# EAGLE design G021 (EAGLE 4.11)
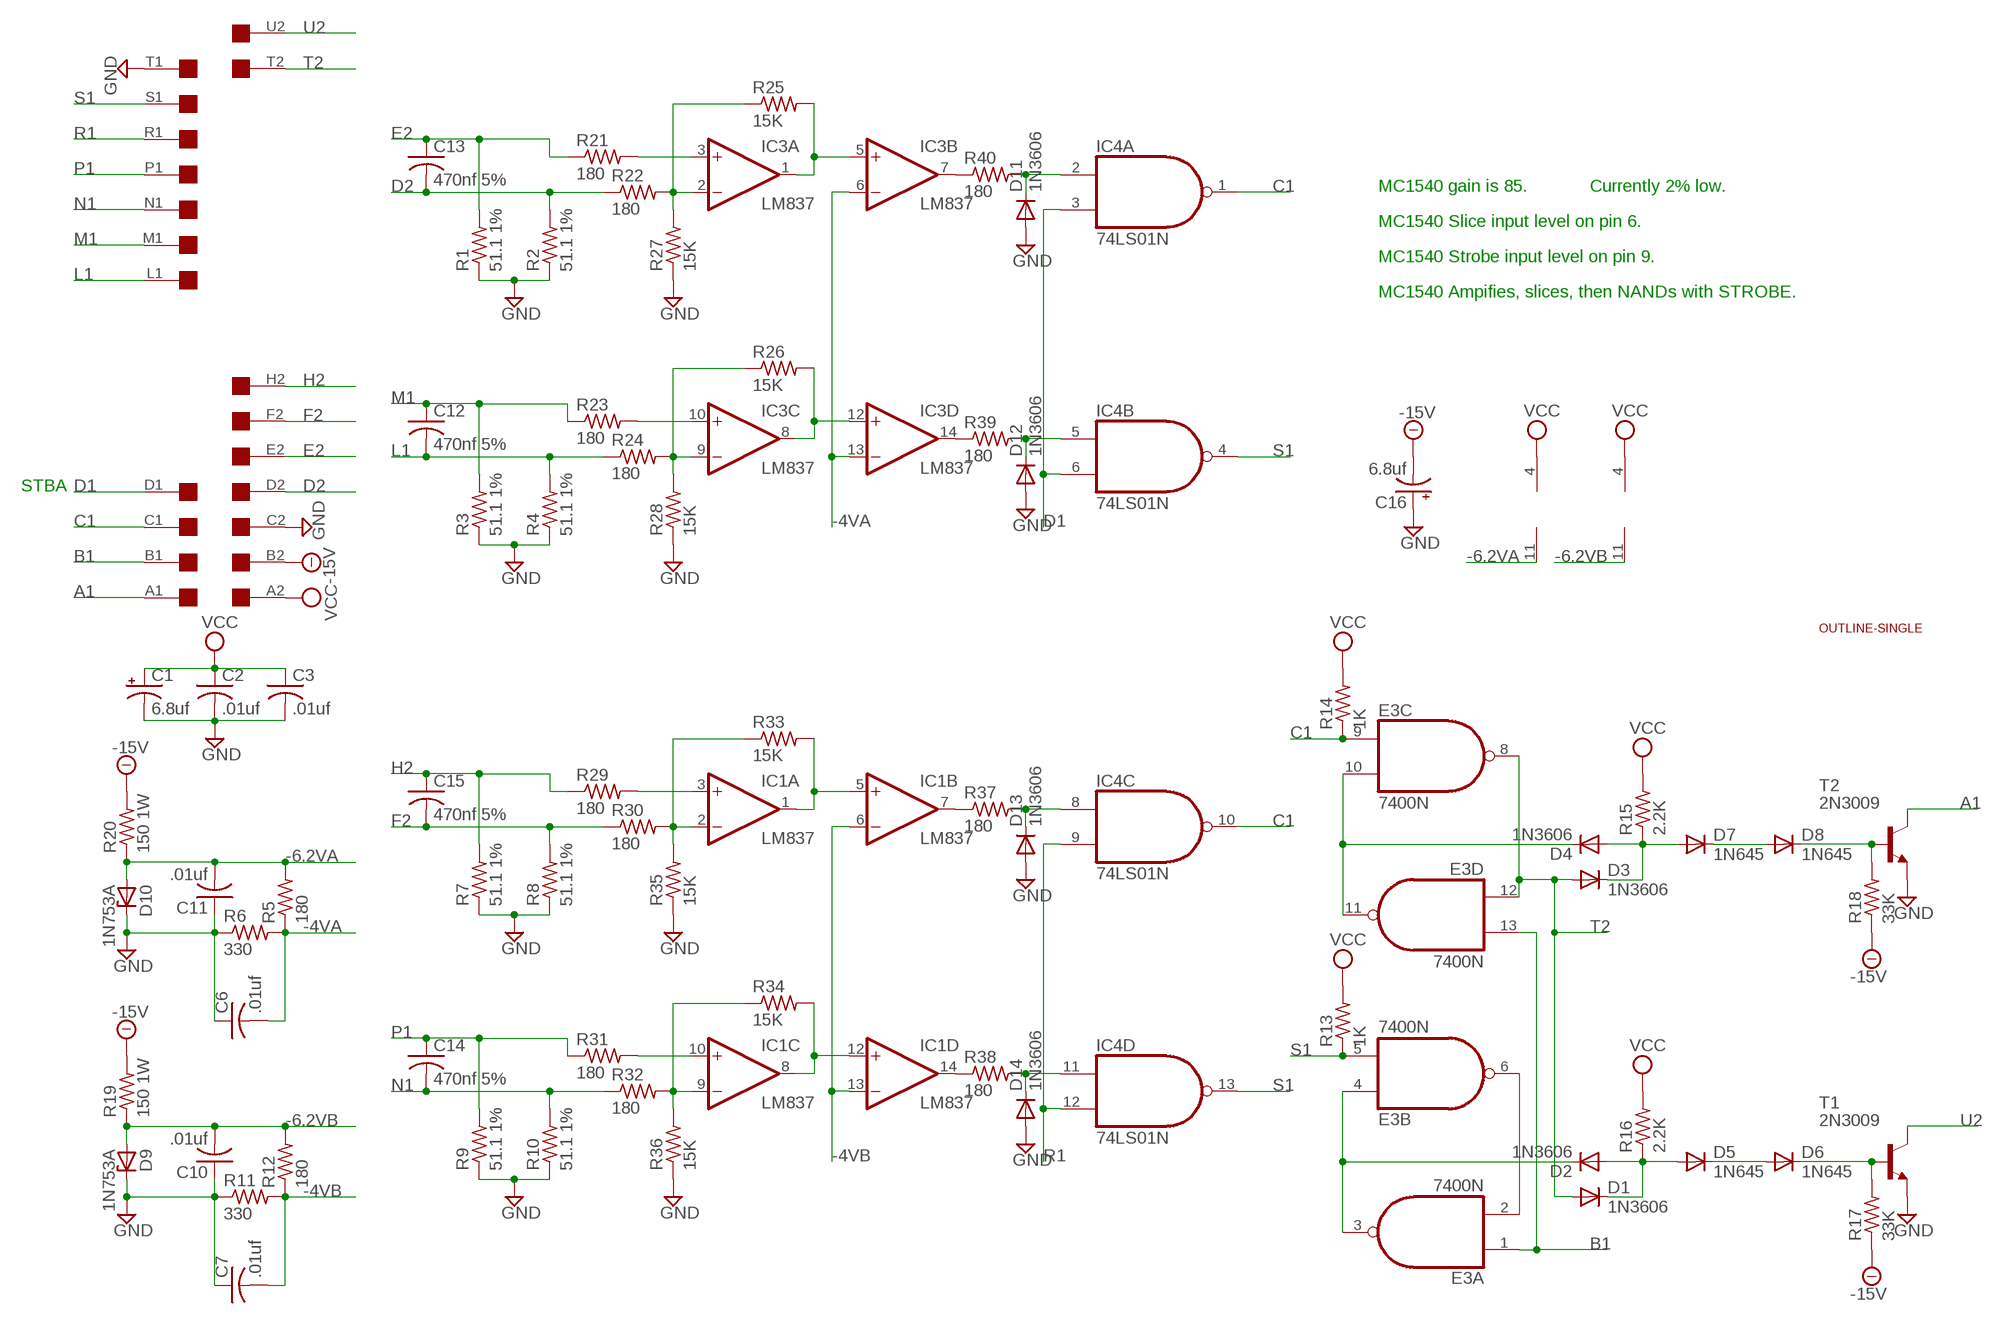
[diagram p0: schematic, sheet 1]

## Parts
C1  6.8uf  CPOL-USE15-5AXIAL  [E15-5]
C2  .01uf  C-US050-025X075  [C050-025X075]
C3  .01uf  C-US050-025X075  [C050-025X075]
C6  .01uf  C-US050-025X075  [C050-025X075]
C7  .01uf  C-US050-025X075  [C050-025X075]
C10  .01uf  C-US050-025X075  [C050-025X075]
C11  .01uf  C-US050-025X075  [C050-025X075]
C12  470nf 5%  C-US050-025X075  [C050-025X075]
C13  470nf 5%  C-US050-025X075  [C050-025X075]
C14  470nf 5%  C-US050-025X075  [C050-025X075]
C15  470nf 5%  C-US050-025X075  [C050-025X075]
C16  6.8uf  CPOL-USE15-5AXIAL  [E15-5]
D1  1N3606  1N4148  [DO35-10]
D2  1N3606  1N4148  [DO35-10]
D3  1N3606  1N4148  [DO35-10]
D4  1N3606  1N4148  [DO35-10]
D5  1N645  1N4148  [DO35-10]
D6  1N645  1N4148  [DO35-10]
D7  1N645  1N4148  [DO35-10]
D8  1N645  1N4148  [DO35-10]
D9  1N753A  ZENER-DIODEF126-10  [F126Z10]
D10  1N753A  ZENER-DIODEF126-10  [F126Z10]
D11  1N3606  1N4148  [DO35-10]
D12  1N3606  1N4148  [DO35-10]
D13  1N3606  1N4148  [DO35-10]
D14  1N3606  1N4148  [DO35-10]
E3  7400N  [DIL14]
IC1  LM837  OP11P  [DIL14]
IC3  LM837  OP11P  [DIL14]
IC4  74LS01N  [DIL14]
R1  51.1 1%  R-US_0207/10  [0207/10]
R2  51.1 1%  R-US_0207/10  [0207/10]
R3  51.1 1%  R-US_0207/10  [0207/10]
R4  51.1 1%  R-US_0207/10  [0207/10]
R5  180  R-US_0207/10  [0207/10]
R6  330  R-US_0207/10  [0207/10]
R7  51.1 1%  R-US_0207/10  [0207/10]
R8  51.1 1%  R-US_0207/10  [0207/10]
R9  51.1 1%  R-US_0207/10  [0207/10]
R10  51.1 1%  R-US_0207/10  [0207/10]
R11  330  R-US_0207/10  [0207/10]
R12  180  R-US_0207/10  [0207/10]
R13  1K  R-US_0207/10  [0207/10]
R14  1K  R-US_0207/10  [0207/10]
R15  2.2K  R-US_0207/10  [0207/10]
R16  2.2K  R-US_0207/10  [0207/10]
R17  33K  R-US_0207/10  [0207/10]
R18  33K  R-US_0207/10  [0207/10]
R19  150 1W  R-US_0414/15  [0414/15]
R20  150 1W  R-US_0414/15  [0414/15]
R21  180  R-US_0207/10  [0207/10]
R22  180  R-US_0207/10  [0207/10]
R23  180  R-US_0207/10  [0207/10]
R24  180  R-US_0207/10  [0207/10]
R25  15K  R-US_0207/10  [0207/10]
R26  15K  R-US_0207/10  [0207/10]
R27  15K  R-US_0207/10  [0207/10]
R28  15K  R-US_0207/10  [0207/10]
R29  180  R-US_0207/10  [0207/10]
R30  180  R-US_0207/10  [0207/10]
R31  180  R-US_0207/10  [0207/10]
R32  180  R-US_0207/10  [0207/10]
R33  15K  R-US_0207/10  [0207/10]
R34  15K  R-US_0207/10  [0207/10]
R35  15K  R-US_0207/10  [0207/10]
R36  15K  R-US_0207/10  [0207/10]
R37  180  R-US_0207/10  [0207/10]
R38  180  R-US_0207/10  [0207/10]
R39  180  R-US_0207/10  [0207/10]
R40  180  R-US_0207/10  [0207/10]
T1  2N3009  2N3565  [TO92]
T2  2N3009  2N3565  [TO92]
U$1  SINGLE  [EDGE-CON2]
U$2  OUTLINE-SINGLE  [SINGLE]

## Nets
-4VA: C6.2 IC3.6(B:-IN) IC3.13(D:-IN) R5.1 R6.2
-4VB: C7.2 IC1.6(B:-IN) IC1.13(D:-IN) R11.2 R12.1
-6.2VA: C11.2 D10.A IC3.11(P:V-) R5.2 R20.1
-6.2VB: C10.2 D9.A IC1.11(P:V-) R12.2 R19.1
-15V: C16.- R17.1 R18.1 R19.2 R20.2 U$1.B2
A1: T2.1(C) U$1.A1
B1: E3.1(A:I0) E3.13(D:I1) U$1.B1
C1: E3.9(C:I0) IC4.1(A:O) IC4.10(C:O) R14.1 U$1.C1
D1: IC4.3(A:I1) IC4.6(B:I1) U$1.D1
D2: C13.2 R2.2 R22.1 U$1.D2
E2: C13.1 R1.2 R21.1 U$1.E2
F2: C15.2 R8.2 R30.1 U$1.F2
GND: C1.- C2.2 C3.2 C6.1 C7.1 C10.1 C11.1 C16.+ D9.C D10.C D11.A D12.A D13.A D14.A R1.1 R2.1 R3.1 R4.1 R6.1 R7.1 R8.1 R9.1 R10.1 R11.1 R27.1 R28.1 R35.1 R36.1 T1.3(E) T2.3(E) U$1.C2 U$1.T1
H2: C15.1 R7.2 R29.1 U$1.H2
L1: C12.2 R4.2 R24.1 U$1.L1
M1: C12.1 R3.2 R23.1 U$1.M1
N1: C14.2 R10.2 R32.1 U$1.N1
N$1: IC3.7(B:OUT) R40.1
N$2: IC3.14(D:OUT) R39.1
N$3: IC1.7(B:OUT) R37.1
N$4: IC1.14(D:OUT) R38.1
N$5: IC3.8(C:OUT) IC3.12(D:+IN) R26.2
N$6: D1.C D2.A D5.A R16.1
N$7: D4.C E3.10(C:I1) E3.11(D:O)
N$8: D2.C E3.3(A:O) E3.4(B:I0)
N$9: E3.2(A:I1) E3.6(B:O)
N$10: D3.C D4.A D7.A R15.1
N$11: D7.C D8.A
N$12: D5.C D6.A
N$13: D8.C R18.2 T2.2(B)
N$14: D6.C R17.2 T1.2(B)
N$15: IC3.1(A:OUT) IC3.5(B:+IN) R25.2
N$20: IC3.9(C:-IN) R24.2 R26.1 R28.2
N$21: IC3.10(C:+IN) R23.2
N$22: IC3.2(A:-IN) R22.2 R25.1 R27.2
N$23: IC3.3(A:+IN) R21.2
N$24: IC1.8(C:OUT) IC1.12(D:+IN) R34.2
N$25: IC1.1(A:OUT) IC1.5(B:+IN) R33.2
N$30: IC1.9(C:-IN) R32.2 R34.1 R36.2
N$31: IC1.10(C:+IN) R31.2
N$32: IC1.2(A:-IN) R30.2 R33.1 R35.2
N$33: IC1.3(A:+IN) R29.2
N$34: D11.C IC4.2(A:I0) R40.2
N$35: D12.C IC4.5(B:I0) R39.2
N$36: D14.C IC4.11(D:I0) R38.2
N$37: D13.C IC4.8(C:I0) R37.2
P1: C14.1 R9.2 R31.1 U$1.P1
R1: IC4.9(C:I1) IC4.12(D:I1) U$1.R1
S1: E3.5(B:I1) IC4.4(B:O) IC4.13(D:O) R13.1 U$1.S1
T2: D1.A D3.A E3.8(C:O) E3.12(D:I0) U$1.T2
U2: T1.1(C) U$1.U2
VCC [supply]: C1.+ C2.1 C3.1 IC1.4(P:V+) IC3.4(P:V+) R13.2 R14.2 R15.2 R16.2 U$1.A2
Unconnected: U$1.E1 U$1.F1 U$1.H1 U$1.J1 U$1.J2 U$1.K1 U$1.K2 U$1.L2 U$1.M2 U$1.N2 U$1.P2 U$1.R2 U$1.S2 U$1.U1 U$1.V1 U$1.V2

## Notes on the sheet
- MC1540 gain is 85. | Currently 2% low.
- MC1540 Slice input level on pin 6.
- MC1540 Strobe input level on pin 9.
- MC1540 Ampifies, slices, then NANDs with STROBE.
- STBA

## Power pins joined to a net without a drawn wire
GND: E3.7(P:GND) IC4.7(P:GND)
VCC: E3.14(P:VCC) IC4.14(P:VCC)

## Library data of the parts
C1 C16 = rcl:CPOL-US: POLARIZED CAPACITOR, American symbol
C2 C3 C6 C7 C10-C15 = rcl:C-US: CAPACITOR, American symbol
D1-D8 D11-D14 = diode:1N4148: DIODE
D9 D10 = diode:ZENER-DIODE: Z-Diode
E3 = 74xx-us:74*00: Quad 2-input NAND gate
IC1 IC3 = linear:OP11: Quad Low-Offset Low-Power OP AMP The OP-11 is pin compatible with the OP-400 , LM148, HA4741, RM4156, and LT1014 operational amplifiers source http://products.analog.com/products/info.asp?product=OP400
IC4 = 74xx-us:74*01: Quad 2-input NAND gate, open collector
R1-R40 = rcl:R-US_: RESISTOR, American symbol
T1 T2 = transistor:2N3565: NPN TRANSISTOR
U$1 = dec-con:SINGLE: Double-Height DEC board
U$2 = dec-con:OUTLINE-*: Board outlines for DEC boards.

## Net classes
1 supply: width 0.762 mm, drill 0.508 mm

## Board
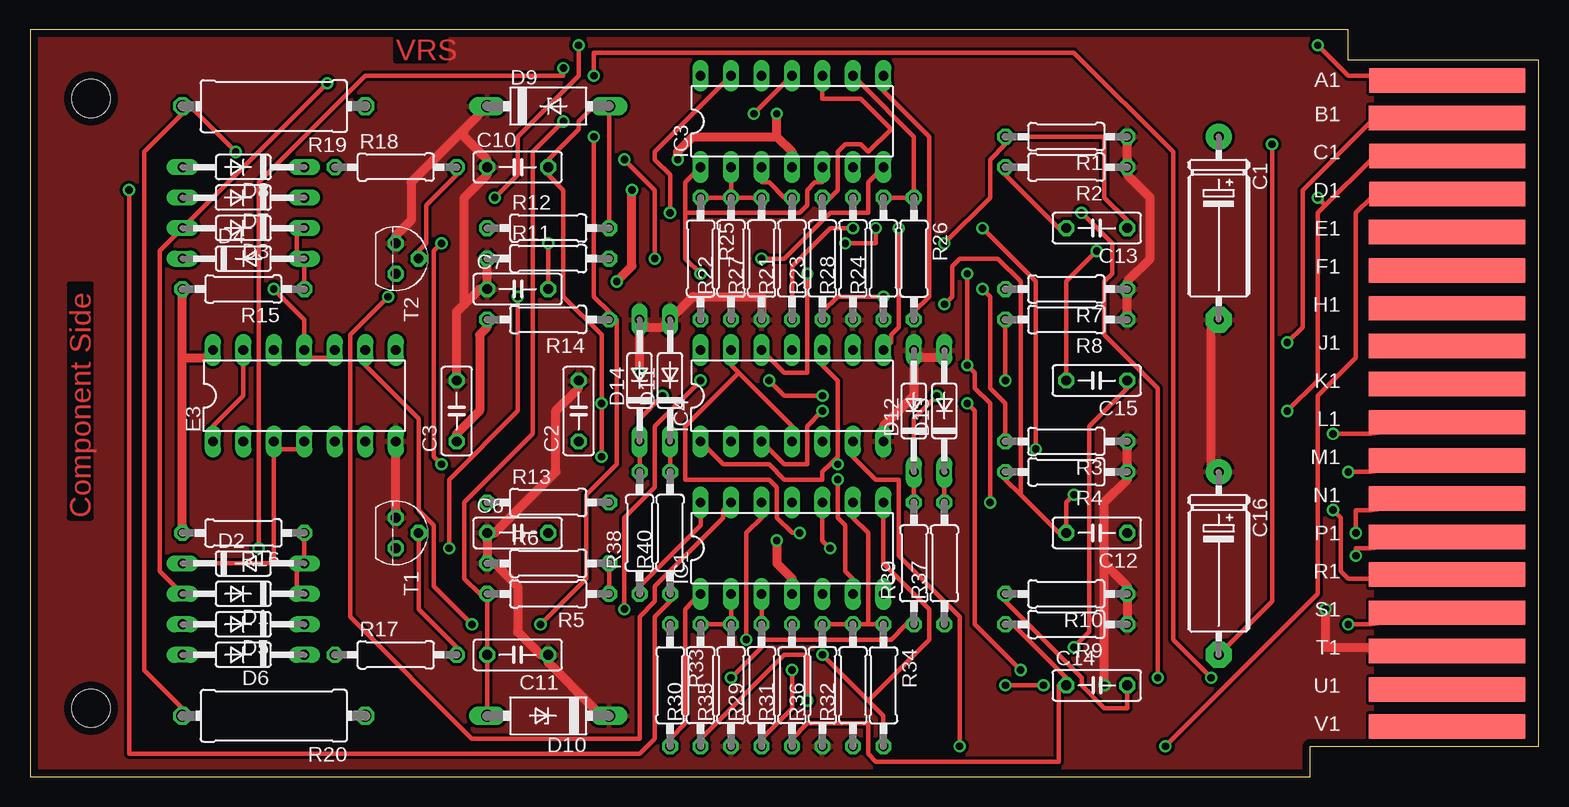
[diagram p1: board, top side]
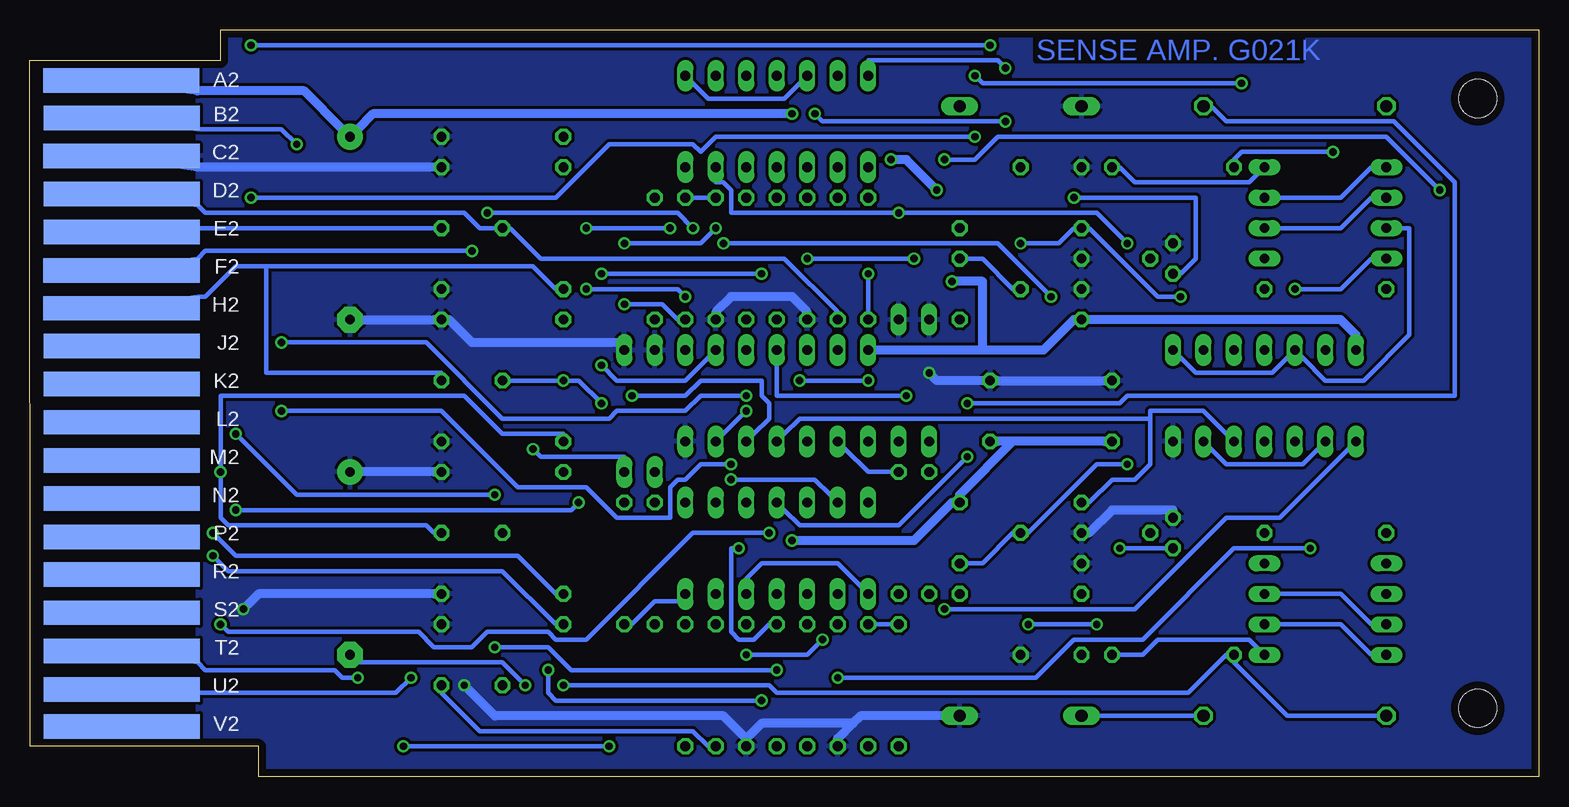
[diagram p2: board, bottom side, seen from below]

Size 125.73 x 62.23 mm. Coordinates in mm from the lower left corner, seen from the top.
Copper layers (1*16): Top 0.035mm / dielectric 1.5mm / Bottom 0.035mm
Design rules "10mils": minimum track width 10mil, minimum drill 24mil, track to track 10mil, track to pad 10mil, pad to pad 10mil, via to via 10mil, smd to smd 10mil, copper to edge 25mil, drill to drill 10mil, minimum pad ring 10mil, minimum via ring 8mil, stop-mask expansion 0mil, vias tented up to drill 0mil, thermal gap 10mil

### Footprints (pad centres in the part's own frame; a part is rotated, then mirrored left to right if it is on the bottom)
E15-5 = drill 0.813 pad 2.159 round: + -7.62,0 | drill 0.813 pad 2.159 octagon: - 7.62,0
C050-025X075 = drill 0.813 octagon: 1 -2.54,0; 2 2.54,0
DO35-10 = drill 0.813 long: A 5.08,0; C -5.08,0
F126Z10 = drill 1.016 long: A 5.08,0; C -5.08,0
DIL14 = drill 0.813 long: 1 -7.62,-3.81; 2 -5.08,-3.81; 3 -2.54,-3.81; 4 0,-3.81; 5 2.54,-3.81; 6 5.08,-3.81; 7 7.62,-3.81; 8 7.62,3.81; 9 5.08,3.81; 10 2.54,3.81; 11 0,3.81; 12 -2.54,3.81; 13 -5.08,3.81; 14 -7.62,3.81
0207/10 = drill 0.813 octagon: 1 -5.08,0; 2 5.08,0
0414/15 = drill 1.016 octagon: 1 -7.62,0; 2 7.62,0
TO92 = drill 0.813 octagon: 1 1.27,0; 2 0,1.905; 3 -1.27,0
EDGE-CON2 = smd 13.017 x 2.032: A1 7.633,4.207; B1 7.639,7.327; C1 7.636,10.489; D1 7.633,13.665; E1 7.642,16.84; F1 7.642,20.041; H1 7.642,23.19; J1 7.642,26.34; K1 7.642,29.515; L1 7.642,32.69; M1 7.642,35.89; N1 7.642,39.04; P1 7.642,42.24; R1 7.642,45.39; S1 7.642,48.565; T1 7.642,51.74; U1 7.642,54.966; V1 7.642,58.026 | smd 13.017 x 2.032 bottom: A2 7.614,4.207; B2 7.642,7.328; C2 7.617,10.49; D2 7.642,13.665; E2 7.642,16.84; F2 7.617,20.041; H2 7.617,23.19; J2 7.642,26.34; K2 7.642,29.515; L2 7.642,32.69; M2 7.642,35.89; N2 7.642,39.04; P2 7.642,42.24; R2 7.642,45.39; S2 7.642,48.565; T2 7.642,51.74; U2 7.642,54.966; V2 7.642,58.026
SINGLE = hole 3.175: 120.65,56.515; 120.65,5.715

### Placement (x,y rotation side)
C1  99.06,45.72 270 top
C2  45.72,30.48 90 top
C3  35.56,30.48 90 top
C6  40.64,20.32 0 top
C7  40.64,40.64 0 top
C10  40.64,50.8 0 top
C11  40.64,10.16 180 top
C12  88.9,20.32 180 top
C13  88.9,45.72 180 top
C14  88.9,7.62 0 top
C15  88.9,33.02 180 top
C16  99.06,17.78 270 top
D1  17.78,15.24 180 top
D2  17.78,17.78 0 top
D3  17.78,45.72 180 top
D4  17.78,43.18 0 top
D5  17.78,12.7 180 top
D6  17.78,10.16 180 top
D7  17.78,48.26 180 top
D8  17.78,50.8 180 top
D9  43.18,55.88 0 top
D10  43.18,5.08 180 top
D11  53.34,33.02 90 top
D12  73.66,30.48 90 top
D13  76.2,30.48 90 top
D14  50.8,33.02 90 top
E3  22.86,31.75 0 top
IC1  63.5,19.05 0 top
IC3  63.5,54.61 0 top
IC4  63.5,31.75 0 top
R1  86.36,53.34 180 top
R2  86.36,50.8 180 top
R3  86.36,27.94 180 top
R4  86.36,25.4 180 top
R5  43.18,15.24 180 top
R6  43.18,17.78 0 top
R7  86.36,40.64 180 top
R8  86.36,38.1 180 top
R9  86.36,12.7 180 top
R10  86.36,15.24 180 top
R11  43.18,43.18 0 top
R12  43.18,45.72 0 top
R13  43.18,22.86 0 top
R14  43.18,38.1 180 top
R15  17.78,40.64 180 top
R16  17.78,20.32 180 top
R17  30.48,10.16 0 top
R18  30.48,50.8 0 top
R19  20.32,55.88 180 top
R20  20.32,5.08 180 top
R21  63.5,43.18 90 top
R22  58.42,43.18 90 top
R23  66.04,43.18 90 top
R24  71.12,43.18 90 top
R25  55.88,43.18 270 top
R26  73.66,43.18 270 top
R27  60.96,43.18 90 top
R28  68.58,43.18 90 top
R29  60.96,7.62 90 top
R30  55.88,7.62 90 top
R31  63.5,7.62 90 top
R32  68.58,7.62 90 top
R33  53.34,7.62 270 top
R34  71.12,7.62 270 top
R35  58.42,7.62 90 top
R36  66.04,7.62 90 top
R37  76.2,17.78 90 top
R38  50.8,20.32 90 top
R39  73.66,17.78 90 top
R40  53.34,20.32 90 top
T1  30.48,20.32 270 top
T2  30.48,43.18 270 top
U$1  125.73,62.23 180 top
U$2  125.73,62.23 180 top

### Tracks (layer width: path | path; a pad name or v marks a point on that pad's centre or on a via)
-4VA  (via drill 0.61)
  Top 0.381: R5.1 48.26,15.88 48.26,17.14 R6.2 | v53.34,46.99 53.34,50.16 52.07,51.44 52.07,52.07 57.78,57.78 IC3.13 | v34.29,26.04 33.66,26.67 33.66,43.81 v34.29,44.45
  Bottom 0.381: R6.2 47.62,17.78 46.35,17.78 43.81,20.32 C6.2 42.55,20.32 36.83,26.04 v34.29,26.04 | IC3.6 68.58,49.53 67.94,49.53 67.31,48.9 67.31,46.99 v53.34,46.99 36.83,46.99 v34.29,44.45
-4VB  (via drill 0.61)
  Top 0.381: v43.18,44.45 43.18,41.27 C7.2 | v67.31,24.77 67.31,21.59 67.94,20.95 67.94,17.14 68.58,16.51 IC1.6 | v29.84,40.01 26.67,36.83 26.67,13.34 36.83,3.17 50.8,3.17 50.8,13.34 52.07,14.61 52.07,15.88 57.78,21.59 57.78,22.23 IC1.13
  Bottom 0.381: C7.2 43.81,40.64 46.35,43.18 47.62,43.18 R11.2 | v43.18,44.45 40.01,44.45 38.73,45.72 R12.1 37.47,45.72 31.75,40.01 v29.84,40.01 | v67.31,24.77 60.33,24.77 59.05,23.5 IC1.13
-6.2VA  (via drill 0.61)
  Top 0.381: D10.A 38.1,5.71 38.1,9.53 C11.2 38.1,10.79 38.1,14.61 R5.2 37.47,15.24 36.2,16.51 36.2,22.86 41.91,28.57 41.91,52.07 v44.45,54.61 | v60.33,55.24 62.87,57.78 IC3.11
  Bottom 0.381: v60.33,55.24 59.69,54.61 v44.45,54.61 | R20.1 28.57,5.08 36.83,5.08 D10.A
-6.2VB  (via drill 0.61)
  Top 0.381: R12.2 48.26,46.35 48.26,55.24 D9.A 46.99,55.88 45.72,54.61 45.72,53.98 43.18,51.44 C10.2 43.18,50.16 44.45,48.9 44.45,40.01 47.62,36.83 v47.62,31.11 v47.62,26.67
  Bottom 0.381: v47.62,26.67 53.34,20.95 61.59,20.95 62.87,22.23 IC1.11 | v47.62,31.11 34.92,31.11 34.29,31.75 6.99,31.75 6.99,49.53 12.06,54.61 26.04,54.61 27.3,55.88 R19.1
-15V  (via drill 0.61)
  Top 0.381: v17.14,52.07 13.34,55.88 R19.2 12.7,55.24 9.53,52.07 9.53,8.89 12.7,5.71 R20.2 | v103.5,52.7 103.5,14.61 99.69,10.79 C16.- | v81.28,7.62 v84.45,7.62
  Bottom 0.381: R20.2 13.34,5.08 20.95,5.08 25.4,9.53 R17.1 26.04,10.16 29.21,6.99 63.5,6.99 64.14,7.62 v81.28,7.62 | v17.14,52.07 24.77,52.07 25.4,51.44 R18.1 | v103.5,52.7 104.78,53.98 111.76,53.98 U$1.B2 | v84.45,7.62 86.36,9.53 98.42,9.53 C16.-
A1  (via drill 0.61)
  Top 0.381: v38.73,48.26 40.64,50.16 40.64,53.34 45.72,58.42 v45.72,60.96 | v107.31,60.96 109.86,58.42 111.76,58.42 U$1.A1
  Bottom 0.381: v38.73,48.26 28.57,48.26 28.57,43.18 29.84,41.91 T2.1 | v45.72,60.96 v107.31,60.96
B1  (via drill 0.61)
  Top 0.381: E3.1 15.24,29.21 17.78,31.75 17.78,34.29 E3.13 | v49.53,13.97 49.53,21.59 52.07,24.13 52.07,29.21 v55.88,33.02 | v61.59,33.02 62.87,31.75 v66.04,31.75 | v104.78,36.2 106.05,37.47 106.05,48.9 111.76,54.61 U$1.B1
  Bottom 0.381: v49.53,13.97 33.66,13.97 26.04,21.59 21.59,21.59 15.88,27.3 E3.1 | v55.88,33.02 v61.59,33.02 | v66.04,31.75 69.85,31.75 71.12,30.48 76.83,30.48 77.47,29.84 86.36,29.84 92.71,36.2 v104.78,36.2
C1  (via drill 0.61)
  Top 0.381: v36.83,12.7 33.66,15.88 33.66,20.95 32.38,22.23 32.38,29.84 27.94,34.29 E3.9 | v42.55,12.7 46.35,16.51 46.35,23.5 48.9,26.04 48.9,38.1 R14.1 48.26,38.73 46.99,40.01 v46.99,53.34 | 66.67,26.04 67.31,26.67 67.31,33.02 66.04,34.29 IC4.10 | 66.67,26.04 66.04,25.4 66.04,24.77 62.87,24.77 61.59,26.04 57.78,26.04 56.52,27.3 IC4.1 | v67.31,26.04 66.67,26.04 | v104.78,30.48 107.31,33.02 107.31,46.99 107.95,47.62 | 107.95,47.62 111.76,51.44 U$1.C1 | v107.31,48.26 107.95,47.62
  Bottom 0.381: v36.83,12.7 v42.55,12.7 | v67.31,26.04 69.85,26.04 71.12,24.77 71.75,24.77 72.39,24.13 72.39,21.59 76.83,21.59 79.38,24.13 85.09,24.13 91.44,30.48 v104.78,30.48 | v46.99,53.34 68.58,53.34 69.85,52.07 70.48,52.7 77.47,52.7 81.92,48.26 v107.31,48.26
D1  (via drill 0.61)
  Top 0.381: v66.04,30.48 64.77,29.21 64.77,26.04 62.87,26.04 61.59,27.3 IC4.3 | v77.47,2.54 77.47,13.34 72.39,18.41 72.39,24.77 70.48,24.77 68.58,26.67 IC4.6 | v94.61,2.54 107.31,15.24 107.31,31.75 110.49,34.92 110.49,46.99 111.76,48.26 U$1.D1
  Bottom 0.381: v66.04,30.48 67.94,28.57 IC4.6 | v77.47,2.54 v94.61,2.54
D2
  Top 0.381: R2.2 81.28,50.16 85.72,45.72 C13.2
  Bottom 0.381: R22.1 58.42,38.73 62.87,43.18 83.19,43.18 85.72,45.72 C13.2 87,45.72 88.27,45.72 89.53,46.99 111.12,46.99 111.76,47.62 U$1.D2
E2  (via drill 0.61)
  Top 0.381: v68.58,45.72 66.67,45.72 63.5,42.55 63.5,38.73 R21.1 | v76.2,44.45 80.01,48.26 80.01,51.44 81.28,52.7 R1.2 81.92,53.34 89.53,53.34 89.53,48.26 91.44,46.35 C13.1
  Bottom 0.381: v68.58,45.72 69.85,44.45 v76.2,44.45 | C13.1 92.08,45.72 111.76,45.72 U$1.E2
F2  (via drill 0.61)
  Top 0.381: v64.77,6.35 64.77,10.16 62.87,10.16 55.88,3.17 R30.1 | v82.55,8.89 78.74,12.7 78.74,30.48 v78.11,31.11 | v81.28,33.02 81.28,37.47 R8.2 | v88.9,43.81 86.36,41.27 86.36,33.66 C15.2
  Bottom 0.381: v64.77,6.35 81.92,6.35 82.55,6.99 v82.55,8.89 | v78.11,31.11 80.01,33.02 v81.28,33.02 85.72,33.02 C15.2 | v88.9,43.81 111.12,43.81 111.76,43.18 U$1.F2
GND  (via drill 0.61)
  Top 0.762: T1.3 30.48,22.23 30.48,26.67 E3.7 | D10.C 46.99,5.08 46.99,5.71 43.18,9.53 C11.1 42.55,10.16 40.64,12.06 40.64,15.88 38.73,17.78 R6.1 38.1,18.41 38.1,19.68 C6.1 38.73,20.32 43.81,25.4 43.81,30.48 45.72,32.38 C2.2 | 36.2,53.98 37.47,55.24 D9.C | 36.2,53.98 31.75,49.53 31.75,46.35 30.48,45.09 T2.3 | 36.2,53.98 36.2,53.34 38.1,51.44 C10.1 38.1,50.16 36.2,48.26 36.2,39.37 | R27.1 60.96,38.73 60.96,40.01 55.24,40.01 53.98,38.73 D11.A 52.7,37.47 51.44,37.47 D14.A 50.8,36.83 v50.8,33.66 | R11.1 38.1,42.55 38.1,41.27 C7.1 37.47,40.64 36.2,39.37 | 36.2,39.37 35.56,38.73 35.56,33.66 C3.2 | R9.1 91.44,13.34 91.44,14.61 R10.1 91.44,15.88 89.53,17.78 | R3.1 91.44,27.3 91.44,26.04 R4.1 91.44,24.77 89.53,22.86 89.53,17.78 | IC4.7 71.12,29.21 73.66,31.75 73.66,34.29 D12.A 74.3,34.92 75.56,34.92 D13.A | R1.1 91.44,52.7 91.44,51.44 R2.1 91.44,50.16 93.34,48.26 93.34,43.18 91.44,41.27 R7.1 91.44,40.01 91.44,38.73 R8.1 | C16.+ 98.42,26.04 98.42,37.47 C1.- | v107.95,13.97 107.95,10.79 111.76,10.79 U$1.T1 | v89.53,7.62 89.53,17.78
  Bottom 0.762: C6.1 37.47,20.32 35.56,22.23 30.48,22.23 T1.3 | 57.15,4.45 56.52,5.08 49.53,5.08 D10.C | 57.15,4.45 58.42,3.17 R35.1 | 66.04,3.17 64.77,4.45 57.15,4.45 | 66.04,3.17 R36.1 66.04,3.17 | R27.1 60.96,38.73 62.23,40.01 67.31,40.01 68.58,38.73 R28.1 | C3.2 36.2,33.02 45.09,33.02 C2.2 46.35,33.02 50.16,33.02 v50.8,33.66 | C16.+ 98.42,25.4 92.08,25.4 R4.1 | C1.- 98.42,38.1 92.08,38.1 R8.1 90.81,38.1 88.9,36.2 76.83,36.2 D13.A | v107.95,13.97 106.68,15.24 92.08,15.24 R10.1 | U$1.C2 111.76,50.8 92.08,50.8 R2.1 | 66.04,3.17 67.94,5.08 87,5.08 v89.53,7.62
  pour Bottom (isolate 0.254): 0,62.23 111.76,62.23 111.76,0 0,0
  pour Top (isolate 0.254): 0,62.23 111.76,62.23 111.76,0 0,0
H2  (via drill 0.61)
  Top 0.381: v63.5,8.89 63.5,5.71 60.96,3.17 R29.1 | v87,10.79 88.27,12.06 88.27,29.21 91.44,32.38 C15.1
  Bottom 0.381: 106.05,42.55 108.58,42.55 111.12,40.01 111.76,40.01 U$1.H2 | 106.05,42.55 83.82,42.55 81.92,40.64 R7.2 | v63.5,8.89 80.64,8.89 82.55,10.79 v87,10.79 | 106.05,42.55 106.05,33.66 91.44,33.66 C15.1
L1  (via drill 0.61)
  Top 0.381: 82.55,23.5 85.72,20.32 C12.2 86.36,20.95 86.36,22.86 v87,23.5 | 82.55,23.5 81.28,24.77 R4.2 | v76.2,39.37 76.83,40.01 76.83,42.55 77.47,43.18 80.64,43.18 82.55,41.27 82.55,23.5 | v108.58,28.57 111.76,28.57 U$1.L1
  Bottom 0.381: v76.2,39.37 73.03,39.37 71.75,38.1 R24.1 | v108.58,28.57 103.5,23.5 v87,23.5
M1  (via drill 0.61)
  Top 0.381: v71.12,40.01 67.31,40.01 66.04,38.73 R23.1 | v79.38,40.64 80.01,40.01 80.01,32.38 81.28,31.11 81.28,28.57 R3.2 | v109.86,25.4 111.76,25.4 U$1.M1
  Bottom 0.381: C12.1 92.08,20.32 92.71,20.95 109.22,20.95 109.86,21.59 v109.86,25.4 109.86,31.75 89.53,31.75 86.36,28.57 81.28,28.57 R3.2 | v71.12,40.01 71.75,40.64 v79.38,40.64
N1  (via drill 0.61)
  Top 0.381: R10.2 81.28,14.61 87.63,8.26 87.63,7.62 89.53,5.71 91.44,5.71 91.44,6.99 C14.2 | v110.49,20.32 110.49,22.23 111.76,22.23 U$1.N1
  Bottom 0.381: R32.1 69.22,2.54 70.48,3.81 88.27,3.81 91.44,6.99 C14.2 | v110.49,20.32 108.58,18.41 85.09,18.41 81.92,15.24 R10.2
N$1  (via drill 0.61)
  Top 0.381: v8.26,48.9 8.26,1.91 50.8,1.91 52.07,3.17 52.07,13.34 53.34,14.61 R40.1 | v49.53,51.44 52.07,48.9 v52.07,43.18 | v60.96,43.18 62.87,43.18 66.67,46.99 69.85,46.99 69.85,49.53 70.48,50.16 IC3.7
  Bottom 0.381: v8.26,48.9 12.7,53.34 45.09,53.34 46.99,51.44 v49.53,51.44 | v52.07,43.18 v60.96,43.18
N$2  (via drill 0.61)
  Top 0.381: v58.42,8.26 60.96,10.79 60.96,11.43 71.75,11.43 73.03,12.7 R39.1 | v19.05,19.05 19.05,49.53 27.94,58.42 44.45,58.42 v44.45,59.05
  Bottom 0.381: v58.42,8.26 41.91,8.26 38.73,11.43 33.02,11.43 25.4,19.05 v19.05,19.05 | v44.45,59.05 45.09,59.69 55.88,59.69 IC3.14
N$3
  Bottom 0.381: R37.1 75.56,12.7 73.66,14.61 71.75,14.61 IC1.7
N$4
  Top 0.381: R38.1 50.8,15.88 55.88,20.95 55.88,21.59 IC1.14
N$5
  Top 0.381: R26.2 73.66,38.73 74.93,40.01 74.93,53.34 71.12,57.15 IC3.8
  Bottom 0.381: IC3.12 61.59,57.78 62.87,56.52 69.22,56.52 70.48,57.78 IC3.8
N$6
  Top 0.381: D1.C 22.23,15.88 22.23,17.14 D2.A 22.86,18.41 22.86,19.68 R16.1
  Bottom 0.381: D5.A 13.97,12.7 16.51,15.24 21.59,15.24 D1.C
N$7  (via drill 0.61)
  Top 0.381: E3.10 24.77,34.92 23.5,34.92 E3.11 22.86,36.83 22.86,38.1 v20.32,40.64
  Bottom 0.381: v20.32,40.64 16.51,40.64 13.97,43.18 D4.C
N$8
  Top 0.381: D2.C 13.97,17.78 20.32,17.78 20.32,26.67 E3.3 20.95,27.3 22.23,27.3 E3.4
N$9
  Bottom 0.381: E3.2 18.41,27.3 19.68,26.04 26.04,26.04 27.3,27.3 E3.6
N$10
  Top 0.381: R15.1 22.86,41.27 22.86,42.55 D4.A 22.23,43.81 22.23,45.09 D3.C
  Bottom 0.381: D7.A 13.97,48.26 16.51,45.72 21.59,45.72 D3.C
N$11
  Bottom 0.381: D8.A 13.97,50.8 16.51,48.26 21.59,48.26 D7.C
N$12
  Bottom 0.381: D6.A 13.97,10.16 16.51,12.7 21.59,12.7 D5.C
N$13
  Top 0.381: T2.2 32.38,43.81 33.02,44.45 33.02,47.62 35.56,50.16 R18.2
  Bottom 0.381: D8.C 23.5,50.16 24.13,49.53 33.66,49.53 34.92,50.8 R18.2
N$14
  Top 0.381: T1.2 32.38,19.68 32.38,13.97 35.56,10.79 R17.2
  Bottom 0.381: D6.C 23.5,10.79 24.13,11.43 31.75,11.43 33.02,10.16 34.92,10.16 R17.2
N$15  (via drill 0.61)
  Top 0.381: v55.88,41.91 54.61,43.18 54.61,46.99 | 54.61,46.99 54.61,49.53 55.24,50.16 IC3.1 | 54.61,46.99 64.14,46.99 64.77,47.62 64.77,48.9 65.41,49.53 66.04,49.53 IC3.5
  Bottom 0.381: v55.88,41.91 55.88,38.73 R25.2
N$20
  Top 0.381: R24.2 71.75,48.26 73.03,48.26 R26.1 73.66,48.9 73.66,53.34 69.22,57.78 IC3.9
  Bottom 0.381: R28.2 69.22,48.26 70.48,48.26 R24.2
N$21
  Top 0.381: R23.2 66.67,48.26 67.31,48.9 67.31,52.07 67.94,52.7 69.22,52.7 69.85,52.07 71.75,53.98 69.22,56.52 66.04,56.52 66.04,57.15 IC3.10
N$22
  Top 0.381: R25.1 56.52,48.26 57.78,48.26 R22.2 | R27.2 60.33,48.26 59.05,48.26 R22.2 | IC3.2 58.42,49.53 58.42,48.9 R22.2
N$23
  Top 0.381: IC3.3 60.96,49.53 61.59,49.53 62.87,48.26 R21.2
N$24  (via drill 0.61)
  Top 0.381: v59.69,11.43 59.69,20.32 60.96,21.59 IC1.12 | 69.85,6.35 71.12,5.08 71.12,3.17 R34.2 | v66.04,10.16 69.85,6.35 | 69.85,6.35 74.93,11.43 74.93,13.97 71.12,17.78 71.12,21.59 IC1.8
  Bottom 0.381: v59.69,11.43 60.96,10.16 v66.04,10.16
N$25
  Top 0.381: R33.2 53.34,3.17 54.61,4.45 54.61,13.97 55.24,14.61 IC1.1
  Bottom 0.381: IC1.5 66.04,16.51 64.77,17.78 58.42,17.78 56.52,15.88 IC1.1
N$30
  Top 0.381: R36.2 66.67,12.7 67.94,12.7 R32.2 69.22,12.7 69.85,12.7 | 69.85,12.7 70.48,12.7 R34.1 | 69.85,12.7 69.85,20.32 68.58,21.59 IC1.9
N$31  (via drill 0.61)
  Top 0.381: v66.67,19.05 66.04,19.68 66.04,21.59 IC1.10
  Bottom 0.381: v66.67,19.05 67.31,19.05 67.31,12.06 66.67,11.43 65.41,11.43 64.14,12.7 R31.2
N$32
  Top 0.381: IC1.2 58.42,13.97 58.42,13.34 R35.2 57.78,12.7 56.52,12.7 R30.2
  Bottom 0.381: R33.1 53.98,12.7 55.24,12.7 R30.2
N$33
  Top 0.381: R29.2 60.96,13.34 60.96,13.97 IC1.3
N$34
  Top 0.381: R40.2 53.34,26.04 53.34,26.67 D11.C
  Bottom 0.381: IC4.2 57.78,27.3 55.88,25.4 53.98,25.4 R40.2
N$35  (via drill 0.61)
  Top 0.381: R39.2 73.66,23.5 73.66,24.13 D12.C 73.66,26.67 73.66,29.84 v75.56,31.75
  Bottom 0.381: v75.56,31.75 71.12,31.75 69.85,33.02 64.77,33.02 64.77,31.75 64.14,31.11 64.14,29.84 65.41,28.57 IC4.5
N$36  (via drill 0.61)
  Top 0.381: R38.2 50.8,26.04 50.8,26.67 D14.C 50.8,29.21 50.8,29.84 v52.7,31.75
  Bottom 0.381: v52.7,31.75 63.5,31.75 63.5,34.29 IC4.11
N$37  (via drill 0.61)
  Top 0.381: R37.2 76.2,23.5 76.2,24.13 D13.C | v72.39,45.72 72.39,37.47 71.75,36.83 71.75,36.2 IC4.8 | v79.38,45.72 83.82,41.27 v83.82,27.3
  Bottom 0.381: v79.38,45.72 v72.39,45.72 | v83.82,27.3 83.19,26.67 76.2,26.67 D13.C
P1  (via drill 0.61)
  Top 0.381: R31.1 63.5,3.17 64.77,4.45 69.85,4.45 69.85,1.91 70.48,1.27 85.72,1.27 85.72,7.62 C14.1 86.36,8.26 81.92,12.7 R9.2 | v110.49,18.41 110.49,19.05 111.76,19.05 U$1.P1
  Bottom 0.381: v110.49,18.41 109.22,17.14 86.36,17.14 81.92,12.7 R9.2
R1  (via drill 0.61)
  Top 0.381: v64.77,41.91 64.77,33.66 62.87,33.66 61.59,34.92 IC4.12 | v78.11,41.91 v78.11,34.29 78.74,33.66 78.74,32.38 80.01,31.11 v80.01,22.86 | v108.58,22.23 109.22,21.59 109.22,17.14 109.86,16.51 111.76,16.51 U$1.R1
  Bottom 0.381: v64.77,41.91 v78.11,41.91 | v78.11,34.29 76.83,33.02 71.12,33.02 69.22,34.92 IC4.9 | v80.01,22.86 80.64,22.23 v108.58,22.23
S1  (via drill 0.61)
  Top 0.381: 59.05,33.66 58.42,34.29 IC4.13 | 59.05,33.66 63.5,29.21 IC4.4 | v109.86,12.7 111.76,12.7 U$1.S1 | v64.14,20.32 63.5,20.32 62.23,21.59 62.23,24.13 61.59,24.77 54.61,24.77 54.61,29.21 59.05,33.66
  Bottom 0.381: 32.38,29.84 32.38,30.48 27.94,30.48 26.04,28.57 E3.5 | 32.38,29.84 32.38,26.04 33.66,24.77 35.56,24.77 37.47,22.86 R13.1 | 32.38,29.84 61.59,29.84 62.87,28.57 IC4.4 | v109.86,12.7 109.22,12.06 93.34,12.06 92.08,10.79 88.9,10.79 87.63,12.06 82.55,12.06 81.92,11.43 79.38,11.43 70.48,20.32 v64.14,20.32
T2  (via drill 0.61)
  Top 0.381: D1.A 12.06,15.88 10.79,17.14 10.79,43.81 12.06,45.09 D3.A 13.34,46.35 v24.77,57.78 | v98.42,8.26 95.25,11.43 95.25,52.07 87,60.33 46.99,60.33 v46.99,58.42
  Bottom 0.381: E3.8 29.84,34.92 28.57,33.66 22.23,33.66 20.95,34.92 E3.12 19.68,34.92 17.78,33.02 14.61,33.02 10.79,36.83 10.79,45.72 11.43,45.72 D3.A | v98.42,8.26 99.69,8.26 100.33,8.89 111.12,8.89 111.76,9.53 U$1.T2 | v46.99,58.42 46.35,57.78 v24.77,57.78
U2  (via drill 0.61)
  Top 0.381: v34.92,19.05 34.92,24.77 40.64,30.48 v40.64,40.01 | v67.94,44.45 70.48,44.45 v70.48,45.72 | v87.63,46.99 90.17,44.45 90.17,41.91 89.53,41.27 89.53,36.83 93.98,32.38 v93.98,8.26
  Bottom 0.381: v34.92,19.05 31.11,19.05 T1.1 | v40.64,40.01 45.09,44.45 v67.94,44.45 | v70.48,45.72 71.75,46.99 v87.63,46.99 | v93.98,8.26 95.25,6.99 111.76,6.99 U$1.U2
VCC  (via drill 0.61)
  Top 0.762: 12.7,34.92 12.7,40.01 R15.2 | 12.7,34.92 12.7,20.95 R16.2 | 12.7,34.92 14.61,34.92 E3.14 | v62.23,19.68 62.23,17.78 63.5,16.51 IC1.4 | R14.2 38.1,37.47 37.47,36.83 37.47,30.48 35.56,28.57 C3.1 | 62.23,53.34 63.5,52.07 IC3.4 | 62.23,53.34 v62.23,55.24 | v48.9,41.27 50.16,42.55 v50.16,48.9 | v53.98,51.44 53.98,52.07 55.24,53.34 62.23,53.34
  Bottom 0.762: 46.35,35.56 55.24,35.56 IC4.14 | 46.35,35.56 41.27,35.56 38.73,38.1 R14.2 37.47,38.1 16.51,38.1 15.24,36.83 E3.14 | 43.81,27.94 45.09,27.94 C2.1 | 43.81,27.94 36.2,27.94 C3.1 | 43.81,27.94 48.26,23.5 R13.2 48.9,22.86 52.07,19.68 v62.23,19.68 | v62.23,55.24 97.16,55.24 98.42,53.98 C1.+ 99.69,53.98 102.87,57.15 111.76,57.15 U$1.A2 | 46.35,35.56 46.35,41.27 v48.9,41.27 | v50.16,48.9 52.7,51.44 v53.98,51.44

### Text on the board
Top: VRS | Component Side
Bottom: SENSE AMP. G021K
